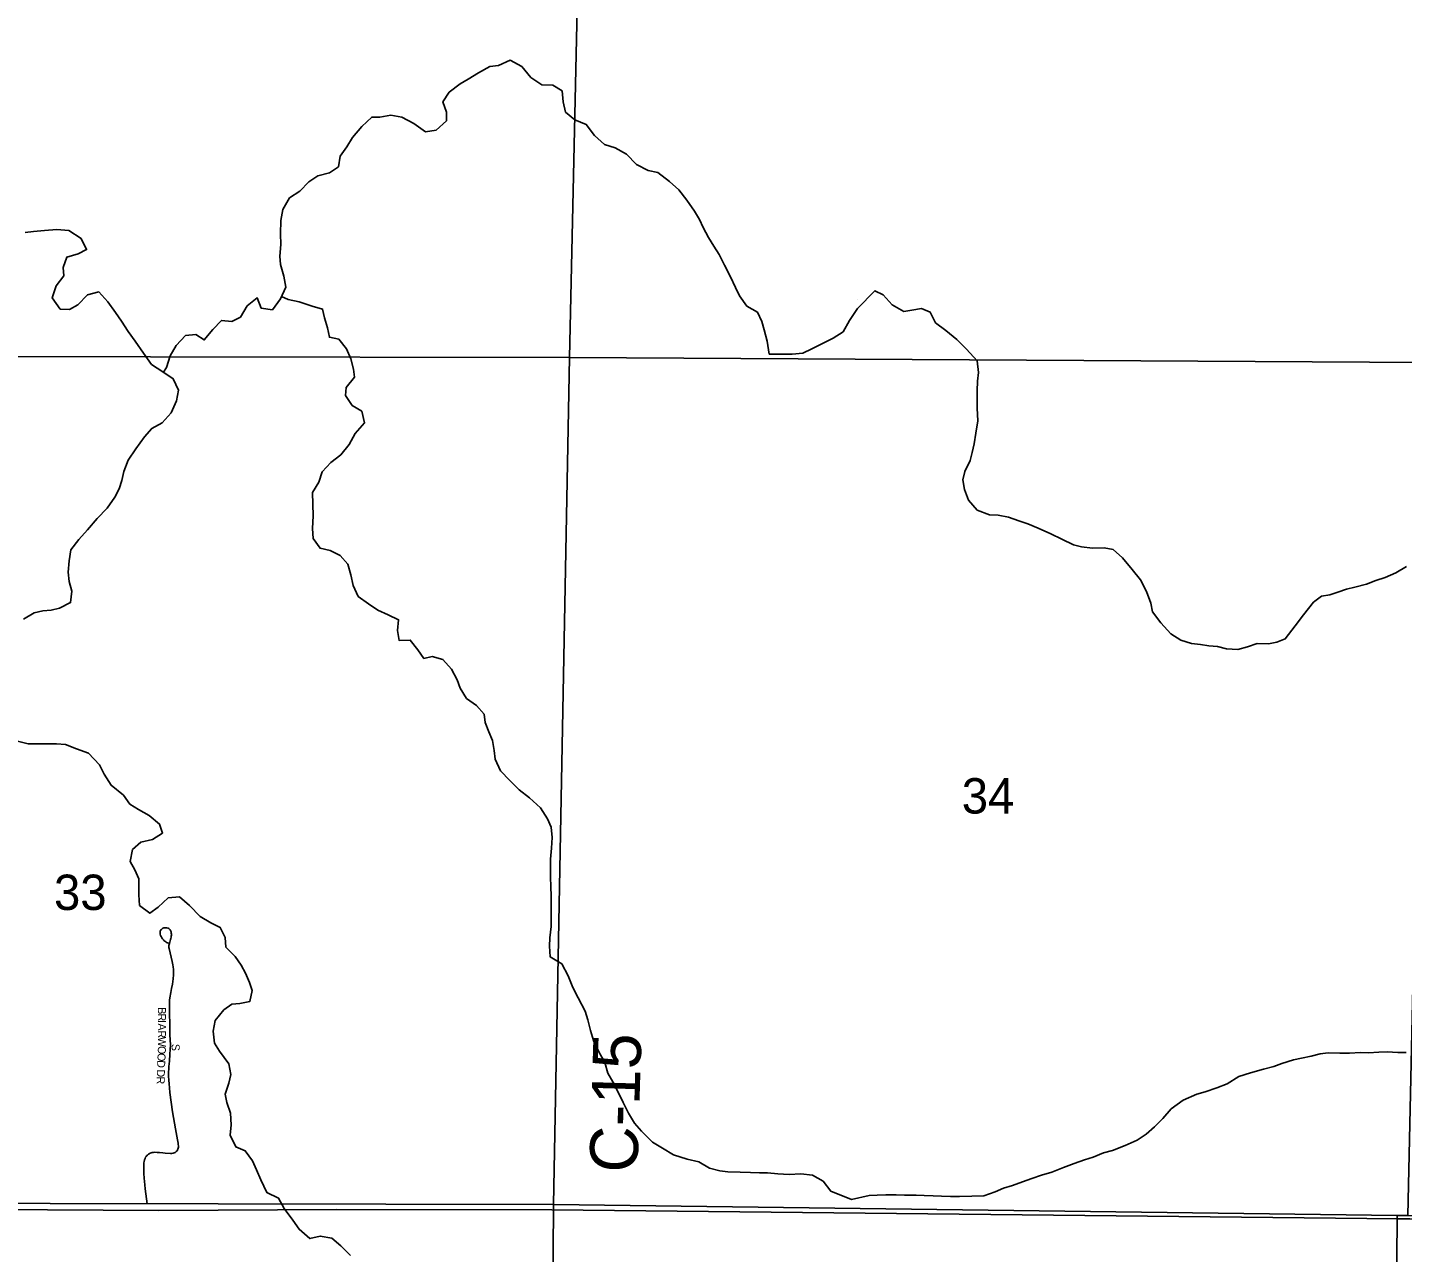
# Model space of a CAD drawing. Extents: x 1772825 to 1773716, y 1138558 to 1139032.
# Drawn here: x 1772829.187 to 1772830.001, y 1138561.109 to 1138561.834 of the extents above; entities that cross this region are included whole.
import ezdxf

# ---------------------------------------------------------------- set-up
doc = ezdxf.new("R2010")
doc.units = 0
for name, color, linetype in [('GM_X_County_Road_Text', 7, 'Continuous'), ('GM_X_Minor_River', 7, 'Continuous'), ('GM_X_Section', 7, 'Continuous'), ('GM_X_Section_Text', 7, 'Continuous'), ('GM_X_Township', 7, 'Continuous'), ('GM_X_Township_Subdivision', 7, 'Continuous'), ('GM_X_Township_Subdivision_Text', 7, 'Continuous')]:
    doc.layers.add(name, color=color, linetype=linetype)

msp = doc.modelspace()

# ---------------------------------------------------------------- linework, layer by layer
at = {"layer": 'GM_X_Minor_River'}
for points in [[(1772829.26766, 1138561.63029), (1772829.26952, 1138561.63303), (1772829.27166, 1138561.64004), (1772829.27512, 1138561.64608), (1772829.28066, 1138561.65192), (1772829.28693, 1138561.65264), (1772829.29184, 1138561.64937), (1772829.29682, 1138561.6556), (1772829.30198, 1138561.66087), (1772829.30804, 1138561.66026), (1772829.31319, 1138561.66287), (1772829.31722, 1138561.66948), (1772829.32313, 1138561.67418), (1772829.32556, 1138561.66809), (1772829.33219, 1138561.6671), (1772829.33698, 1138561.6737), (1772829.34007, 1138561.68051), (1772829.33898, 1138561.68716), (1772829.33694, 1138561.694), (1772829.3366, 1138561.69894), (1772829.33721, 1138561.70576), (1772829.33688, 1138561.71222), (1772829.33713, 1138561.72), (1772829.33831, 1138561.72644), (1772829.34235, 1138561.73343), (1772829.34845, 1138561.73737), (1772829.35361, 1138561.74283), (1772829.35895, 1138561.7464), (1772829.36598, 1138561.74824), (1772829.37132, 1138561.75181), (1772829.37232, 1138561.75806), (1772829.37615, 1138561.76353), (1772829.37961, 1138561.7692), (1772829.38497, 1138561.77561), (1772829.39089, 1138561.78126), (1772829.39563, 1138561.78122), (1772829.40228, 1138561.78231), (1772829.40872, 1138561.78112), (1772829.41572, 1138561.77747), (1772829.4227, 1138561.77248), (1772829.42897, 1138561.77357), (1772829.43508, 1138561.77903), (1772829.43512, 1138561.78415), (1772829.43307, 1138561.79024), (1772829.43672, 1138561.7959), (1772829.44321, 1138561.80079), (1772829.44797, 1138561.8036), (1772829.45407, 1138561.80735), (1772829.46074, 1138561.81109), (1772829.46587, 1138561.81181), (1772829.47291, 1138561.81498), (1772829.47971, 1138561.81114), (1772829.48498, 1138561.80465), (1772829.49159, 1138561.80023), (1772829.49804, 1138561.80019), (1772829.50351, 1138561.79673), (1772829.50423, 1138561.79027), (1772829.50551, 1138561.78419), (1772829.51117, 1138561.77959), (1772829.51779, 1138561.77689), (1772829.52268, 1138561.7704), (1772829.52871, 1138561.76504), (1772829.53495, 1138561.7631), (1772829.54157, 1138561.75925), (1772829.54759, 1138561.75314), (1772829.5544, 1138561.74967), (1772829.56027, 1138561.74849), (1772829.56706, 1138561.74312), (1772829.57253, 1138561.73815), (1772829.57742, 1138561.73204), (1772829.58193, 1138561.72555), (1772829.58493, 1138561.7206), (1772829.58698, 1138561.71584), (1772829.59016, 1138561.70993), (1772829.59335, 1138561.70479), (1772829.59654, 1138561.69983), (1772829.59972, 1138561.69354), (1772829.60308, 1138561.68669), (1772829.60607, 1138561.6804), (1772829.6085, 1138561.67545), (1772829.61282, 1138561.66935), (1772829.61906, 1138561.6657), (1772829.62168, 1138561.66036), (1772829.62316, 1138561.65542), (1772829.62481, 1138561.64858), (1772829.62609, 1138561.64098), (1772829.63975, 1138561.64087), (1772829.64601, 1138561.64159), (1772829.65134, 1138561.64401), (1772829.66391, 1138561.65037), (1772829.66982, 1138561.65412), (1772829.67367, 1138561.66092), (1772829.67837, 1138561.66798)], [(1772829.18586, 1138561.71297), (1772829.1908, 1138561.71351), (1772829.19725, 1138561.71403), (1772829.20466, 1138561.71473), (1772829.21167, 1138561.71411), (1772829.21904, 1138561.70931), (1772829.22222, 1138561.70283), (1772829.21726, 1138561.70022), (1772829.21061, 1138561.69837), (1772829.20829, 1138561.69212), (1772829.20882, 1138561.68738), (1772829.20422, 1138561.68134), (1772829.2019, 1138561.67434), (1772829.20659, 1138561.66747), (1772829.21209, 1138561.66743), (1772829.21704, 1138561.67005), (1772829.22278, 1138561.67608), (1772829.22943, 1138561.67773), (1772829.2347, 1138561.67181), (1772829.2394, 1138561.66552), (1772829.24278, 1138561.66056), (1772829.24672, 1138561.65427), (1772829.25104, 1138561.64854), (1772829.25592, 1138561.64148), (1772829.26062, 1138561.63481), (1772829.26723, 1138561.63058), (1772829.27346, 1138561.62636), (1772829.27663, 1138561.6197), (1772829.27545, 1138561.61326), (1772829.27217, 1138561.60626), (1772829.267, 1138561.60023), (1772829.26072, 1138561.59705), (1772829.25651, 1138561.59196), (1772829.25134, 1138561.58498), (1772829.24673, 1138561.57818), (1772829.24422, 1138561.57156), (1772829.24304, 1138561.56626), (1772829.24149, 1138561.56133), (1772829.23898, 1138561.55642), (1772829.23438, 1138561.54981), (1772829.22846, 1138561.54379), (1772829.22272, 1138561.537), (1772829.21755, 1138561.53135), (1772829.21295, 1138561.52512), (1772829.21196, 1138561.51867), (1772829.21134, 1138561.51204), (1772829.21187, 1138561.50653), (1772829.21353, 1138561.50064), (1772829.21273, 1138561.494), (1772829.20625, 1138561.49064), (1772829.20131, 1138561.48953), (1772829.19637, 1138561.489), (1772829.19124, 1138561.4879), (1772829.18495, 1138561.48416)], [(1772829.67837, 1138561.66798), (1772829.68858, 1138561.67843), (1772829.6935, 1138561.67613), (1772829.69879, 1138561.67022), (1772829.7058, 1138561.66621), (1772829.71055, 1138561.66695), (1772829.71625, 1138561.66787), (1772829.72136, 1138561.66576), (1772829.72456, 1138561.65949), (1772829.73062, 1138561.65491), (1772829.73705, 1138561.64957), (1772829.74272, 1138561.64385), (1772829.74914, 1138561.63699), (1772829.74987, 1138561.63015), (1772829.74928, 1138561.62503), (1772829.74907, 1138561.61934), (1772829.74904, 1138561.61384), (1772829.74921, 1138561.6089), (1772829.74956, 1138561.6015), (1772829.74839, 1138561.59429), (1772829.74742, 1138561.58784), (1772829.74607, 1138561.58272), (1772829.74491, 1138561.57799), (1772829.74184, 1138561.57154), (1772829.74068, 1138561.56662), (1772829.74161, 1138561.56092), (1772829.74405, 1138561.55446), (1772829.74915, 1138561.54855), (1772829.75635, 1138561.54586), (1772829.76147, 1138561.54565), (1772829.76773, 1138561.54449), (1772829.7738, 1138561.54237), (1772829.7791, 1138561.54064), (1772829.78517, 1138561.53796), (1772829.79274, 1138561.5347), (1772829.79918, 1138561.53145), (1772829.80619, 1138561.52819), (1772829.81093, 1138561.52685), (1772829.81738, 1138561.52625), (1772829.82422, 1138561.52641), (1772829.82953, 1138561.52544), (1772829.8352, 1138561.52048), (1772829.84086, 1138561.51363), (1772829.84577, 1138561.50734), (1772829.84935, 1138561.50049), (1772829.85179, 1138561.49365), (1772829.85291, 1138561.48852), (1772829.85781, 1138561.48205), (1772829.86367, 1138561.47538), (1772829.86954, 1138561.47175), (1772829.87598, 1138561.46983), (1772829.88129, 1138561.46924), (1772829.88622, 1138561.46846), (1772829.89135, 1138561.46806), (1772829.89666, 1138561.46651), (1772829.9033, 1138561.46611), (1772829.909, 1138561.46779), (1772829.9147, 1138561.46966), (1772829.92153, 1138561.46964), (1772829.92647, 1138561.47056), (1772829.93141, 1138561.47244), (1772829.93733, 1138561.4802), (1772829.94229, 1138561.48663), (1772829.94802, 1138561.4942), (1772829.95277, 1138561.49778), (1772829.95771, 1138561.49852), (1772829.96247, 1138561.50021), (1772829.9676, 1138561.50189), (1772829.97254, 1138561.50301), (1772829.97938, 1138561.50488), (1772829.98508, 1138561.50694), (1772829.99059, 1138561.50882), (1772829.99686, 1138561.51164), (1772830.00314, 1138561.51522)], [(1772829.33757, 1138561.675), (1772829.34153, 1138561.67329), (1772829.34797, 1138561.67191), (1772829.35573, 1138561.66938), (1772829.36179, 1138561.66763), (1772829.36289, 1138561.6625), (1772829.36475, 1138561.6566), (1772829.36585, 1138561.6509), (1772829.37153, 1138561.64972), (1772829.37604, 1138561.64419), (1772829.37846, 1138561.6381), (1772829.38013, 1138561.63201), (1772829.38066, 1138561.62726), (1772829.37587, 1138561.62123), (1772829.37546, 1138561.61649), (1772829.3794, 1138561.61058), (1772829.38507, 1138561.60712), (1772829.38654, 1138561.60028), (1772829.38118, 1138561.59406), (1772829.37753, 1138561.58744), (1772829.37255, 1138561.58141), (1772829.36664, 1138561.5769), (1772829.36166, 1138561.57124), (1772829.35953, 1138561.56519), (1772829.35588, 1138561.55914), (1772829.35602, 1138561.55212), (1772829.35635, 1138561.54529), (1772829.35592, 1138561.53789), (1772829.35625, 1138561.53182), (1772829.36038, 1138561.5261), (1772829.36625, 1138561.52472), (1772829.37231, 1138561.52183), (1772829.37682, 1138561.51667), (1772829.37848, 1138561.5104), (1772829.37996, 1138561.50413), (1772829.38294, 1138561.49765), (1772829.38898, 1138561.49324), (1772829.39446, 1138561.48941), (1772829.4007, 1138561.48671), (1772829.40675, 1138561.48381), (1772829.40613, 1138561.47737), (1772829.40723, 1138561.47148), (1772829.41368, 1138561.47181), (1772829.41819, 1138561.46608), (1772829.42176, 1138561.46093), (1772829.4267, 1138561.46203), (1772829.43295, 1138561.46028), (1772829.43803, 1138561.45455), (1772829.4414, 1138561.44826), (1772829.44326, 1138561.44331), (1772829.44701, 1138561.43722), (1772829.45286, 1138561.433), (1772829.45738, 1138561.42784), (1772829.4581, 1138561.42309), (1772829.46015, 1138561.41757), (1772829.46239, 1138561.41243), (1772829.46329, 1138561.40636), (1772829.46402, 1138561.40123), (1772829.467, 1138561.39437), (1772829.47265, 1138561.38864), (1772829.47811, 1138561.3831), (1772829.48434, 1138561.37849), (1772829.49075, 1138561.37257), (1772829.49488, 1138561.36608), (1772829.49712, 1138561.36113), (1772829.49764, 1138561.35487), (1772829.49722, 1138561.34861), (1772829.4966, 1138561.34216), (1772829.49675, 1138561.33685), (1772829.49671, 1138561.33192), (1772829.49686, 1138561.32565), (1772829.49701, 1138561.32072), (1772829.49716, 1138561.31446), (1772829.49707, 1138561.30232), (1772829.49626, 1138561.29568), (1772829.49603, 1138561.29075), (1772829.49656, 1138561.2843), (1772829.50336, 1138561.28026), (1772829.5071, 1138561.27302), (1772829.50989, 1138561.26617), (1772829.51308, 1138561.26008), (1772829.51719, 1138561.25227), (1772829.51886, 1138561.24713), (1772829.52034, 1138561.24086), (1772829.52219, 1138561.23477), (1772829.52518, 1138561.22811), (1772829.52873, 1138561.22182), (1772829.53059, 1138561.21555), (1772829.53358, 1138561.2104), (1772829.5362, 1138561.20545), (1772829.53976, 1138561.19821), (1772829.54275, 1138561.19193), (1772829.54631, 1138561.18602), (1772829.55045, 1138561.18125), (1772829.55704, 1138561.17475), (1772829.56289, 1138561.1711), (1772829.56951, 1138561.16725), (1772829.57746, 1138561.16473), (1772829.58447, 1138561.16297), (1772829.5907, 1138561.15931), (1772829.59695, 1138561.15775)], [(1772829.67816, 1138561.67304), (1772829.67817, 1138561.67305)], [(1772829.18139, 1138561.41189), (1772829.18764, 1138561.41033), (1772829.19296, 1138561.41048), (1772829.20434, 1138561.41039), (1772829.20965, 1138561.40997), (1772829.21627, 1138561.40746), (1772829.22327, 1138561.40494), (1772829.22986, 1138561.39787)], [(1772829.22986, 1138561.39787), (1772829.23267, 1138561.39253), (1772829.23679, 1138561.38586), (1772829.24396, 1138561.37993), (1772829.24772, 1138561.37478), (1772829.25282, 1138561.37151), (1772829.25924, 1138561.36805), (1772829.26528, 1138561.36288), (1772829.26713, 1138561.35755), (1772829.26123, 1138561.3538), (1772829.25438, 1138561.35215), (1772829.24942, 1138561.34782), (1772829.24804, 1138561.34081), (1772829.25066, 1138561.33586), (1772829.25309, 1138561.33053), (1772829.25302, 1138561.32104), (1772829.25354, 1138561.31478), (1772829.25958, 1138561.31018), (1772829.26454, 1138561.31374), (1772829.27046, 1138561.3192), (1772829.27711, 1138561.31991), (1772829.28314, 1138561.31474), (1772829.28935, 1138561.30824), (1772829.29578, 1138561.3044), (1772829.30126, 1138561.3017), (1772829.30425, 1138561.2958), (1772829.30459, 1138561.2901), (1772829.31005, 1138561.28456), (1772829.31362, 1138561.27941), (1772829.31624, 1138561.27465), (1772829.31867, 1138561.26913), (1772829.32015, 1138561.26437), (1772829.31877, 1138561.25793), (1772829.31288, 1138561.25684), (1772829.30814, 1138561.25631), (1772829.30337, 1138561.25293), (1772829.2982, 1138561.2467), (1772829.29702, 1138561.24045), (1772829.29791, 1138561.23324), (1772829.30091, 1138561.22847), (1772829.30636, 1138561.22103), (1772829.30764, 1138561.21476), (1772829.30628, 1138561.20965), (1772829.30414, 1138561.20302), (1772829.30525, 1138561.19827), (1772829.30729, 1138561.19181), (1772829.30781, 1138561.18497), (1772829.30719, 1138561.1789), (1772829.31056, 1138561.17186), (1772829.31604, 1138561.16954), (1772829.32036, 1138561.16363), (1772829.32279, 1138561.1583), (1772829.32521, 1138561.1524), (1772829.32876, 1138561.14497), (1772829.33576, 1138561.1415), (1772829.33913, 1138561.13541), (1772829.3442, 1138561.12854), (1772829.34796, 1138561.1232), (1772829.35437, 1138561.11765), (1772829.36045, 1138561.11912), (1772829.36727, 1138561.11793), (1772829.37255, 1138561.11334), (1772829.37839, 1138561.1076)], [(1772829.67474, 1138561.14081), (1772829.68519, 1138561.14308), (1772829.68994, 1138561.14344), (1772829.69507, 1138561.14361), (1772829.70114, 1138561.14359), (1772829.70607, 1138561.14338), (1772829.7131, 1138561.14335), (1772829.71784, 1138561.14314), (1772829.72315, 1138561.14293), (1772829.72809, 1138561.14271), (1772829.7334, 1138561.1425), (1772829.73871, 1138561.14248), (1772829.74593, 1138561.14283), (1772829.75314, 1138561.14299), (1772829.75979, 1138561.14524), (1772829.76474, 1138561.14749), (1772829.77006, 1138561.14899), (1772829.77595, 1138561.15124), (1772829.78146, 1138561.15312), (1772829.78716, 1138561.15518), (1772829.79325, 1138561.15686), (1772829.80028, 1138561.15968), (1772829.80655, 1138561.16212), (1772829.81263, 1138561.16418), (1772829.81777, 1138561.16587), (1772829.82385, 1138561.16831), (1772829.82917, 1138561.1698), (1772829.83677, 1138561.17281), (1772829.84381, 1138561.17582), (1772829.84914, 1138561.1794), (1772829.85409, 1138561.18374), (1772829.85905, 1138561.18865), (1772829.86382, 1138561.19433), (1772829.87105, 1138561.19961), (1772829.87904, 1138561.20318), (1772829.88398, 1138561.20449), (1772829.89101, 1138561.20693), (1772829.89709, 1138561.20918), (1772829.90394, 1138561.21352), (1772829.91079, 1138561.21576), (1772829.91857, 1138561.21782), (1772829.92466, 1138561.2195), (1772829.92941, 1138561.22119), (1772829.93625, 1138561.22344), (1772829.941, 1138561.22437), (1772829.9467, 1138561.22567), (1772829.95202, 1138561.22698), (1772829.95676, 1138561.22753), (1772829.9636, 1138561.22731), (1772829.96948, 1138561.22728), (1772829.97593, 1138561.22782), (1772829.98068, 1138561.22761), (1772829.98675, 1138561.22797), (1772829.99169, 1138561.22814), (1772829.99795, 1138561.22773), (1772830.00288, 1138561.22771)], [(1772829.59695, 1138561.15775), (1772829.60169, 1138561.15715), (1772829.6089, 1138561.1569), (1772829.61497, 1138561.15667), (1772829.62028, 1138561.15663), (1772829.62502, 1138561.15659), (1772829.63109, 1138561.15597), (1772829.63791, 1138561.15554), (1772829.64475, 1138561.15606), (1772829.65176, 1138561.15525), (1772829.658, 1138561.1516), (1772829.66251, 1138561.14568), (1772829.67474, 1138561.14081)]]:
    msp.add_lwpolyline(points, dxfattribs=at)
at = {"layer": 'GM_X_Section'}
for points in [[(1772829.51894, 1138562.14124), (1772829.50793, 1138561.63902), (1772829.0119, 1138561.63975), (1772829.02215, 1138562.14292)], [(1772829.51894, 1138562.14124), (1772830.02062, 1138562.14047), (1772830.01505, 1138561.63594), (1772829.50793, 1138561.63902)], [(1772829.50793, 1138561.63902), (1772829.49844, 1138561.13775), (1772829.00204, 1138561.13886), (1772829.0119, 1138561.63975)], [(1772829.50793, 1138561.63902), (1772830.01505, 1138561.63594), (1772830.00399, 1138561.13125), (1772829.99754, 1138561.13129), (1772829.49844, 1138561.13775)], [(1772828.99654, 1138561.1389), (1772829.00204, 1138561.13886), (1772829.49844, 1138561.13775), (1772829.49493, 1138560.62469), (1772828.98978, 1138560.62246)], [(1772829.49844, 1138561.13775), (1772829.99754, 1138561.13129), (1772829.99388, 1138560.62883), (1772829.49493, 1138560.62469)], [(1772829.99754, 1138561.13129), (1772830.00399, 1138561.13125), (1772830.4951, 1138561.13106), (1772830.48689, 1138560.63014), (1772829.99388, 1138560.62883)]]:
    msp.add_lwpolyline(points, close=True, dxfattribs=at)
at = {"layer": 'GM_X_Township'}
for points in [[(1772831.01894, 1138562.12536), (1772831.01622, 1138561.62783), (1772831.01179, 1138561.12989), (1772830.51059, 1138561.12809), (1772830.49526, 1138561.12804), (1772830.00504, 1138561.12927), (1772829.99819, 1138561.12929), (1772829.49747, 1138561.13472), (1772829.37021, 1138561.13493), (1772829.26496, 1138561.13428), (1772828.93513, 1138561.13617)], [(1772828.93513, 1138561.13617), (1772829.26496, 1138561.13428), (1772829.37021, 1138561.13493), (1772829.49747, 1138561.13472), (1772829.99819, 1138561.12929), (1772830.00504, 1138561.12927), (1772830.49526, 1138561.12804), (1772830.51059, 1138561.12809), (1772831.01179, 1138561.12989), (1772831.00806, 1138560.6364), (1772831.00657, 1138560.43995), (1772831.00428, 1138560.13753), (1772830.99963, 1138559.63002)]]:
    msp.add_lwpolyline(points, dxfattribs=at)
at = {"layer": 'GM_X_Township_Subdivision'}
msp.add_lwpolyline([(1772829.25801, 1138561.13816), (1772829.25719, 1138561.14422), (1772829.25692, 1138561.14701), (1772829.25661, 1138561.14947), (1772829.25631, 1138561.15348), (1772829.25615, 1138561.15621), (1772829.25603, 1138561.15906), (1772829.256, 1138561.1605), (1772829.25616, 1138561.16249), (1772829.25629, 1138561.16332), (1772829.25651, 1138561.16432), (1772829.25678, 1138561.16503), (1772829.25713, 1138561.16573), (1772829.25751, 1138561.16626), (1772829.25787, 1138561.16672), (1772829.25827, 1138561.1671), (1772829.2588, 1138561.16752), (1772829.25929, 1138561.16783), (1772829.25988, 1138561.16812), (1772829.26048, 1138561.16834), (1772829.26106, 1138561.1685), (1772829.26172, 1138561.16861), (1772829.2626, 1138561.16869), (1772829.26398, 1138561.16863), (1772829.2654, 1138561.16854), (1772829.26724, 1138561.16838), (1772829.26873, 1138561.16823), (1772829.27183, 1138561.16796), (1772829.27262, 1138561.16799), (1772829.27338, 1138561.16812), (1772829.27395, 1138561.16832), (1772829.27463, 1138561.16867), (1772829.27519, 1138561.1691), (1772829.2757, 1138561.16964), (1772829.27607, 1138561.17015), (1772829.27627, 1138561.17058), (1772829.27642, 1138561.17124), (1772829.2765, 1138561.1718), (1772829.2765, 1138561.17247), (1772829.27642, 1138561.17328), (1772829.27629, 1138561.17413), (1772829.27594, 1138561.17602), (1772829.27473, 1138561.18261), (1772829.27304, 1138561.19264), (1772829.27144, 1138561.20416), (1772829.27119, 1138561.20687), (1772829.27097, 1138561.20927), (1772829.27081, 1138561.21139), (1772829.27069, 1138561.21374), (1772829.27069, 1138561.21616), (1772829.27079, 1138561.21803), (1772829.2709, 1138561.21945), (1772829.27118, 1138561.2227), (1772829.27155, 1138561.22669), (1772829.27176, 1138561.23232), (1772829.2715, 1138561.23816), (1772829.27139, 1138561.24466), (1772829.27125, 1138561.25058), (1772829.27116, 1138561.25403), (1772829.27122, 1138561.25671), (1772829.27132, 1138561.25868), (1772829.2715, 1138561.26004), (1772829.27208, 1138561.26316), (1772829.27249, 1138561.26559), (1772829.27294, 1138561.2682), (1772829.27319, 1138561.26974), (1772829.27339, 1138561.27135), (1772829.2736, 1138561.27373), (1772829.27372, 1138561.27542), (1772829.27368, 1138561.27685), (1772829.27347, 1138561.27838), (1772829.27322, 1138561.27964), (1772829.27278, 1138561.28168), (1772829.27223, 1138561.2842), (1772829.27108, 1138561.28935), (1772829.27096, 1138561.28995), (1772829.2709, 1138561.29044), (1772829.2709, 1138561.29106), (1772829.271, 1138561.29168), (1772829.27117, 1138561.29234), (1772829.27139, 1138561.29307), (1772829.27162, 1138561.29388), (1772829.27182, 1138561.2946), (1772829.27203, 1138561.29523), (1772829.27217, 1138561.29593), (1772829.27228, 1138561.29649), (1772829.27236, 1138561.29719), (1772829.27238, 1138561.29785), (1772829.27232, 1138561.29844), (1772829.27221, 1138561.29907), (1772829.27207, 1138561.29959), (1772829.27168, 1138561.30025), (1772829.27129, 1138561.30068), (1772829.27081, 1138561.30105), (1772829.27038, 1138561.3013), (1772829.26972, 1138561.3015), (1772829.26919, 1138561.30159), (1772829.26857, 1138561.30159), (1772829.26796, 1138561.30146), (1772829.26738, 1138561.30126), (1772829.26689, 1138561.30099), (1772829.26648, 1138561.30062), (1772829.26619, 1138561.30027), (1772829.26594, 1138561.29986), (1772829.26581, 1138561.2995), (1772829.26565, 1138561.2989), (1772829.26565, 1138561.29832), (1772829.26576, 1138561.29769), (1772829.26596, 1138561.29704), (1772829.26625, 1138561.29641), (1772829.26668, 1138561.29568), (1772829.26714, 1138561.29503), (1772829.26761, 1138561.29445), (1772829.26796, 1138561.29408), (1772829.26841, 1138561.29367), (1772829.26903, 1138561.2932), (1772829.26944, 1138561.29293), (1772829.27008, 1138561.29263), (1772829.27086, 1138561.29238)], dxfattribs=at)

# ---------------------------------------------------------------- texts
at = {"layer": 'GM_X_County_Road_Text'}
msp.add_text('C-15', height=0.028409, rotation=88.30675, dxfattribs=at).set_placement((1772829.5481, 1138561.15639))
at = {"layer": 'GM_X_Section_Text'}
for s, p in [('34', (1772829.74, 1138561.36915)), ('33', (1772829.20292, 1138561.31207))]:
    msp.add_text(s, height=0.020928, rotation=0.00001, dxfattribs=at).set_placement(p)
at = {"layer": 'GM_X_Township_Subdivision_Text'}
for s, rotation, p in [('B', 270, (1772829.26441, 1138561.25454)), ('R', 269.99405, (1772829.26441, 1138561.25079)), ('I', 270, (1772829.26441, 1138561.24704)), ('A', 269.99284, (1772829.26441, 1138561.24496)), ('W', 269.93274, (1772829.26441, 1138561.23704)), ('R', 269.99405, (1772829.26441, 1138561.24079)), ('O', 268.84155, (1772829.2644, 1138561.23165)), ('S', 270, (1772829.27256, 1138561.23287)), ('D', 267.38073, (1772829.26407, 1138561.2233)), ('O', 266.56679, (1772829.26432, 1138561.22753)), ('R', 269.57836, (1772829.26371, 1138561.21353)), ('D', 268.29262, (1772829.26384, 1138561.21781))]:
    msp.add_text(s, height=0.00473, rotation=rotation, dxfattribs=at).set_placement(p)

doc.saveas('drawing.dxf')
